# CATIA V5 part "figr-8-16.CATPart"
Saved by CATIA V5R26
Part number: Part1
Bounding box of the stored display mesh (mm): x -55.501 to 55.501, y -84.223 to 84.223, z 0 to 81
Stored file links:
  D:\_Deepak\CATIA\CATIA V5-6R2016_Deepak\Resources\Part files\Partfiles\c08_catia_v5_6r2016_prt\figr-8-16.CATPart
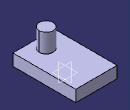
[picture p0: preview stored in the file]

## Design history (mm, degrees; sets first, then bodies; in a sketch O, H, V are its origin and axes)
Body1 (main body)
  Sketch1 on xy-plane, origin (0, 0, 0), H (1, 0, 0), V (0, 1, 0)
    line L1 (-55.501, 84.2232) -> (55.501, 84.2232)
    line L2 (55.501, 84.2232) -> (55.501, -84.2232)
    line L3 (55.501, -84.2232) -> (-55.501, -84.2232)
    line L4 (-55.501, -84.2232) -> (-55.501, 84.2232)
    axis line L5 (55.501, -84.2232) -> (-55.501, 84.2232)
    horizontal: L1 H, L3 H
    vertical: L2 V, L4 V
    midpoint: O L5
  Pad1: profile Sketch1, direction (0, 0, 1), length 31
  Sketch2 on face of Pad1, origin (0, 0, 31), H (1, 0, 0), V (0, 1, 0)
    circle A1 centre (0, -50.4568) radius 18.9426
    point P1 (0, -50.4568)
    coincidence: P1 V
  Pad2: profile Sketch2, direction (0, 0, 1), length 50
